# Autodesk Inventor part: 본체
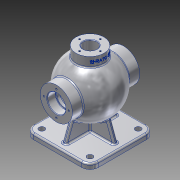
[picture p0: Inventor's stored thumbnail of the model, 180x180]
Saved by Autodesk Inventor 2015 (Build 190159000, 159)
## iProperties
Created: 2025-08
Part Number: 본체
Material: 알루미늄 6061
Document SubType Name: Modeling
Designer: USER
Density: 2.7 g/cm^3
Appearance: 알루미늄 - 평지
Author: USER
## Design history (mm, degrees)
sketch "스케치1"
  geometry: L1 (-62.5, 62.5)-(62.5, 62.5); L2 (62.5, 62.5)-(62.5, -62.5); L3 (62.5, -62.5)-(-62.5, -62.5); L4 (-62.5, -62.5)-(-62.5, 62.5); L5 (-62.5, 62.5)-(62.5, -62.5); L6 (62.5, 62.5)-(-62.5, -62.5); 1 further point
  constraints: 12 end point, 2 midpoint, 2 parallel, 1 horizontal, 1 perpendicular
  dimensions: "d0" = 125 distance of L2.end L3.end; "d1" = 125 distance of L1.end L2.end
extrude "돌출1" new body sketch "스케치1" distance "d2" = 10; taper "d3" = 0 deg
sketch "스케치2"
  geometry: L1 (62.5, 10)-(62.5, 0) reference; L2 (62.5, 0)-(-62.5, 0) reference; L3 (-62.5, 0)-(-62.5, 10) reference; L4 (-62.5, 10)-(62.5, 10) reference; L5 (0, 139)-(0, 31); A1 r 54 centre (0, 85) between (0, 139) and (0, 31); 3 further points
  constraints: 2 end point, 2 midpoint, 2 point on circle, 1 centre point, 1 coincident, 1 vertical, 1 vertical alignment
  dimensions: "d4" = 108 diameter of A1; "d5" = 85 distance from line of A1.centre L2
revolve "회전1" sketch "스케치2" stored, may be unused: angle "d6" = 90 deg
sketch "스케치5"
  geometry: L1 (-4, -50.5)-(4, -50.5); L2 (4, -50.5)-(4, 50.5); L3 (4, 50.5)-(-4, 50.5); L4 (-4, 50.5)-(-4, -50.5); L5 (-4, -50.5)-(4, 50.5); L6 (4, -50.5)-(-4, 50.5); L7 (-50.5, -4)-(50.5, -4); L8 (50.5, -4)-(50.5, 4); L9 (50.5, 4)-(-50.5, 4); L10 (-50.5, 4)-(-50.5, -4); L11 (-50.5, -4)-(50.5, 4); L12 (50.5, -4)-(-50.5, 4); L13 (-62.5, -62.5)-(-62.5, 62.5) reference; L14 (-62.5, 62.5)-(62.5, 62.5) reference; 1 further point
  constraints: 24 end point, 4 midpoint, 4 parallel, 2 horizontal, 2 perpendicular
  dimensions: "d15" = 12 distance between parallel lines of L10 L13; "d16" = 12 distance between parallel lines of L3 L14; "d17" = 8 distance between parallel lines of L9 L7; "d18" = 8 distance between parallel lines of L4 L2
extrude "돌출4" join sketch "스케치5" distance "d19" = 85; taper "d20" = 0 deg
feature "면 기울기1" dims angle "d21" = 20 deg
node "작업 평면1"
sketch "스케치6"
  geometry: L1 (-25.074, 11.167)-(16.405, 11.167); L2 (16.405, 11.167)-(16.405, 5.163); L3 (16.405, 5.163)-(-25.074, 5.163); L4 (-25.074, 5.163)-(-25.074, 11.167); C1 r 27 at (0, 0); 1 further point
  constraints: 1 centre point, 1 coincident, 2 other
  dimensions: "d23" = 54 diameter of C1
extrude "돌출5" join sketch "스케치6" stored distance "d24" = 85; taper "d25" = 0 deg
node "작업 평면2"
sketch "스케치7"
  geometry: C1 r 31 at (0, 85); 1 further point
  constraints: 1 centre point, 1 vertical alignment
  dimensions: "d27" = 62 diameter of C1; "d28" = 85 distance of C1.centre point (0, 0)
extrude "돌출6" join sketch "스케치7" distance "d29" = 130; taper "d30" = 0 deg
hole "구멍1" diameter "d39" = 30; stored, may be unused: countersink angle "d43" = 90 deg, drill point angle "d45" = 0 deg; dims "d37" = 10, "d38" = 10, "d40" = 6, "d41" = 35, "d42" = 16, "d44" = 8
hole "구멍2" diameter "d48" = 26; stored, may be unused: countersink angle "d52" = 90 deg, drill point angle "d54" = 0 deg; dims "d46" = 10, "d47" = 10, "d49" = 6, "d50" = 35, "d51" = 16, "d53" = 100
sketch "스케치10"
  geometry: L1 (0, 0)-(0, 24); 1 further point
  constraints: 2 end point, 1 vertical
  dimensions: "d55" = 24 distance of L1.start L1.end
hole "구멍3" sketch "스케치10" at (0, 24) diameter "d56" = 3.242; stored, may be unused: countersink angle "d60" = 90 deg, drill point angle "d62" = 118 deg; dims "d57" = 12, "d58" = 35, "d59" = 16, "d61" = 15
sketch "스케치11"
  geometry: L1 (0, 0)-(0, 20)
  constraints: 2 end point, 1 vertical
  dimensions: "d66" = 20 distance of L1.start L1.end
hole "구멍4" sketch "스케치11" at (0, 20) diameter "d67" = 3.242; stored, may be unused: countersink angle "d71" = 90 deg, drill point angle "d73" = 118 deg; dims "d68" = 9, "d69" = 35, "d70" = 16, "d72" = 11
fillet "모깎기1" dims "d78" = 16
hole "구멍5" diameter "d81" = 11; stored, may be unused: countersink angle "d85" = 90 deg, drill point angle "d87" = 0 deg; dims "d79" = 10, "d80" = 10, "d82" = 203.2, "d83" = 35, "d84" = 16, "d86" = 11
hole "구멍6" diameter "d90" = 11; stored, may be unused: countersink angle "d94" = 90 deg, drill point angle "d96" = 0 deg; dims "d88" = 10, "d89" = 10, "d91" = 203.2, "d92" = 35, "d93" = 16, "d95" = 11
hole "구멍7" diameter "d99" = 11; stored, may be unused: countersink angle "d103" = 90 deg, drill point angle "d105" = 0 deg; dims "d97" = 10, "d98" = 10, "d100" = 203.2, "d101" = 35, "d102" = 16, "d104" = 11
hole "구멍8" diameter "d108" = 11; stored, may be unused: countersink angle "d112" = 90 deg, drill point angle "d114" = 0 deg; dims "d106" = 10, "d107" = 10, "d109" = 203.2, "d110" = 35, "d111" = 16, "d113" = 11
sketch "스케치13"
  geometry: L1 (-13, 150)-(13, 150) reference; 3 further points
  constraints: 1 midpoint, 1 vertical alignment, 1 other
  dimensions: "d115" = 9 distance from line of point (0, 141) L1
feature "엠보싱1" sketch "스케치13" dims "d0" = 125, "d1" = 125, "d16" = 12, "d18" = 8, "d116" = 0.5, "d117" = 0
chamfer "모따기1" distance "d118" = 1; stored, may be unused: second distance "d119" = 2, angle "d120" = 45 deg
fillet "모깎기2" dims "d121" = 0.6
fillet "모깎기3" dims "d122" = 3
fillet "모깎기4" dims "d123" = 3
sketch "스케치14"
  geometry: L1 (50, 110.621)-(49.026, 109) reference; L2 (49.026, 109)-(50, 107.379) reference; L3 (50, 107.379)-(65, 107.379) reference; L4 (65, 107.379)-(65, 103.5) reference; L5 (65, 103.5)-(64, 102.5) reference; L6 (64, 102.5)-(49.6, 102.5) reference; L7 (49, 101.9)-(49, 100) reference; L8 (49, 100)-(13, 100) reference; L9 (13, 100)-(13, 149) reference; L10 (13, 149)-(14, 150) reference; L11 (14, 150)-(18.379, 150) reference; L12 (18.379, 150)-(18.379, 139) reference; L13 (18.379, 139)-(20, 138.026) reference; L14 (20, 138.026)-(21.621, 139) reference; L15 (21.621, 139)-(21.621, 150) reference; L16 (21.621, 150)-(27, 150) reference; L17 (27, 150)-(27, 133.466) reference; L18 (45.749, 116)-(65, 116) reference; L19 (65, 116)-(65, 110.621) reference; L20 (65, 110.621)-(50, 110.621) reference; L21 (-49.026, 109)-(-50, 110.621) reference; L22 (-50, 110.621)-(-65, 110.621) reference; L23 (-65, 110.621)-(-65, 116) reference; L24 (-65, 116)-(-45.749, 116) reference; L25 (-27, 133.466)-(-27, 150) reference; L26 (-27, 150)-(-21.621, 150) reference; L27 (-21.621, 150)-(-21.621, 139) reference; L28 (-21.621, 139)-(-20, 138.026) reference; L29 (-20, 138.026)-(-18.379, 139) reference; L30 (-18.379, 139)-(-18.379, 150) reference; L31 (-18.379, 150)-(-14, 150) reference; L32 (-14, 150)-(-13, 149) reference; L33 (-13, 149)-(-13, 100) reference; L34 (-13, 100)-(-49, 100) reference; L35 (-49, 100)-(-49, 101.9) reference; L36 (-49.6, 102.5)-(-64, 102.5) reference; L37 (-64, 102.5)-(-65, 103.5) reference; L38 (-65, 103.5)-(-65, 107.379) reference; L39 (-65, 107.379)-(-50, 107.379) reference; L40 (-50, 107.379)-(-49.026, 109) reference; L41 (-13, 70)-(-13, 50) reference; L42 (-13, 50)-(13, 50) reference; L43 (13, 50)-(13, 70) reference; L44 (13, 70)-(49, 70) reference; L45 (49, 70)-(49, 68.1) reference; L46 (49.6, 67.5)-(64, 67.5) reference; L47 (64, 67.5)-(65, 66.5) reference; L48 (65, 66.5)-(65, 62.621) reference; L49 (65, 62.621)-(50, 62.621) reference; L50 (50, 62.621)-(49.026, 61) reference; L51 (49.026, 61)-(50, 59.379) reference; L52 (50, 59.379)-(65, 59.379) reference; L53 (65, 59.379)-(65, 54) reference; L54 (65, 54)-(45.749, 54) reference; L55 (37.385, 46.034)-(49.782, 11.974) reference; L56 (52.601, 10)-(59.5, 10) reference; L57 (62.5, 7)-(62.5, 0) reference; L58 (62.5, 0)-(-62.5, 0) reference; L59 (-62.5, 0)-(-62.5, 7) reference; L60 (-59.5, 10)-(-52.601, 10) reference; L61 (-49.782, 11.974)-(-37.385, 46.034) reference; L62 (-45.749, 54)-(-65, 54) reference; L63 (-65, 54)-(-65, 59.379) reference; L64 (-65, 59.379)-(-50, 59.379) reference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; A1 r 0.6 centre (49.6, 101.9) between (49.6, 102.5) and (49, 101.9) reference; A2 r 3 centre (30, 133.466) between (27, 133.466) and (28.421, 130.916) reference; A3 r 54 centre (0, 85) between (43.341, 117.211) and (28.421, 130.916) reference; A4 r 3 centre (45.749, 119) between (43.341, 117.211) and (45.749, 116) reference; A5 r 3 centre (-45.749, 119) between (-45.749, 116) and (-43.341, 117.211) reference; A6 r 54 centre (0, 85) between (-28.421, 130.916) and (-43.341, 117.211) reference; A7 r 3 centre (-30, 133.466) between (-28.421, 130.916) and (-27, 133.466) reference; A8 r 0.6 centre (-49.6, 101.9) between (-49, 101.9) and (-49.6, 102.5) reference; A9 r 0.6 centre (49.6, 68.1) between (49, 68.1) and (49.6, 67.5) reference; A10 r 3 centre (45.749, 51) between (45.749, 54) and (43.341, 52.789) reference; A11 r 54 centre (0, 85) between (37.385, 46.034) and (43.341, 52.789) reference; A12 r 3 centre (52.601, 13) between (49.782, 11.974) and (52.601, 10) reference; A13 r 3 centre (59.5, 7) between (62.5, 7) and (59.5, 10) reference; A14 r 3 centre (-59.5, 7) between (-59.5, 10) and (-62.5, 7) reference; A15 r 3 centre (-52.601, 13) between (-52.601, 10) and (-49.782, 11.974) reference; A16 r 54 centre (0, 85) between (-43.341, 52.789) and (-37.385, 46.034) reference; A17 r 3 centre (-45.749, 51) between (-43.341, 52.789) and (-45.749, 54) reference; A18 r 0.6 centre (-49.6, 68.1) between (-49.6, 67.5) and (-49, 68.1) reference; A19 r 44 centre (0, 85) between (-1, 41.011) and (-1, 128.989); A20 r 45.21 centre (0, 85) between (-42.649, 100) and (-42.474, 100.488); A21 r 44 centre (0, 85) between (-42.164, 97.579) and (-43.326, 92.674); 1 further point
  constraints: 6 point on circle, 5 point on line, 3 centre point, 2 end point, 1 coincident, 1 concentric, 1 vertical
  dimensions: "d125" = 44 radius of A19
revolve "회전2" sketch "스케치14" stored, may be unused: angle "d126" = 90 deg
sketch "스케치15"
  geometry: 1 further point
fillet "모깎기5" dims "d127" = 3
node "솔리드1"
mirror "대칭1"
pattern_circular "원형 패턴1" dims angle "d64" = 360 deg
mirror "대칭2"
pattern_circular "원형 패턴2" dims angle "d75" = 360 deg
node "절단 모서리 투영1"
node "절단 모서리 투영2"
other parameters: "d26" = -65, "d124" = 88
